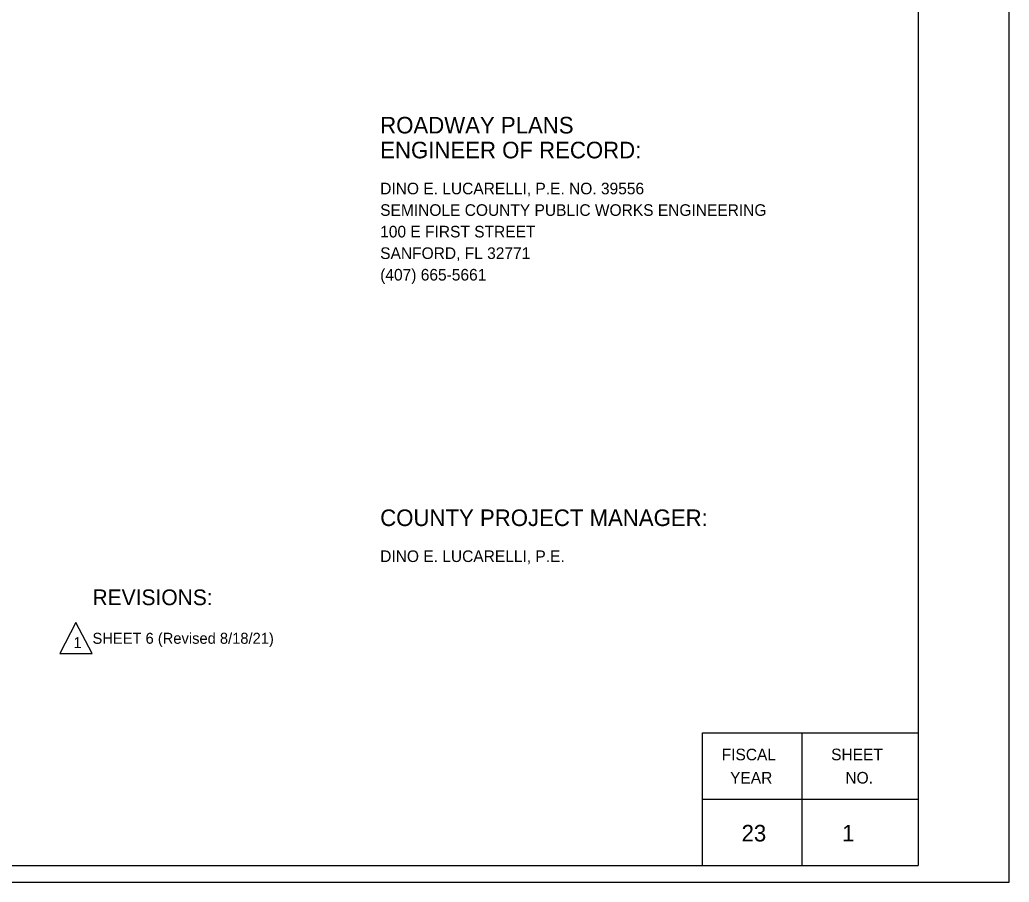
# Model space of a CAD drawing. Extents: x 2157516 to 2331756, y 2153820 to 2265756.
# Drawn here: x 2268726 to 2331756, y 2153820 to 2208739 of the extents above; entities that cross this region are included whole.
import ezdxf

# ---------------------------------------------------------------- set-up
doc = ezdxf.new("R2010")
doc.units = 0
for name, color, linetype in [('NonPlottingEle_dp', 7, 'Continuous'), ('PlotBorder_dp', 7, 'Continuous'), ('SheetBorder_dp', 7, 'Continuous'), ('SheetLines_dp', 7, 'Continuous'), ('TextLabel', 7, 'Continuous'), ('TextNotes', 7, 'Continuous'), ('TextShtNo', 7, 'Continuous')]:
    doc.layers.add(name, color=color, linetype=linetype)

msp = doc.modelspace()

# ---------------------------------------------------------------- linework, layer by layer
at = {"layer": 'NonPlottingEle_dp'}
msp.add_lwpolyline([(2272307, 2170353), (2271280, 2168375), (2273334, 2168375)], close=True, dxfattribs=at)
at = {"layer": 'PlotBorder_dp'}
msp.add_lwpolyline([(2157516, 2153820), (2331756, 2153820), (2331756, 2265756), (2157516, 2265756)], close=True, dxfattribs=at)
at = {"layer": 'SheetBorder_dp'}
for p in [(2325948, 2264700), (2163324, 2154876)]:
    msp.add_line(p, (2325948, 2154876), dxfattribs=at)
at = {"layer": 'SheetLines_dp'}
for p, q in [((2312220, 2163324), (2325948, 2163324)), ((2312220, 2154876), (2312220, 2163324)), ((2318556, 2154876), (2318556, 2163324)), ((2312220, 2159100), (2325948, 2159100))]:
    msp.add_line(p, q, dxfattribs=at)

# ---------------------------------------------------------------- texts
at = {"layer": 'NonPlottingEle_dp'}
for s, height, p in [('REVISIONS:', 1000, (2273359, 2171462)), ('SHEET 6 (Revised 8/18/21)                               ', 700, (2273359, 2169002)), ('1', 700, (2272146, 2168727))]:
    msp.add_text(s, height=height, dxfattribs=at).set_placement(p)
at = {"layer": 'TextLabel'}
for s, p in [('ROADWAY PLANS', (2291686, 2201501)), ('ENGINEER OF RECORD:', (2291686, 2199917)), ('COUNTY PROJECT MANAGER:', (2291686, 2176500))]:
    msp.add_text(s, height=1056, dxfattribs=at).set_placement(p)
at = {"layer": 'TextNotes'}
for s, p in [('DINO E. LUCARELLI, P.E. NO. 39556', (2291686, 2197625)), ('SEMINOLE COUNTY PUBLIC WORKS ENGINEERING', (2291686, 2196253)), ('100 E FIRST STREET', (2291686, 2194880)), ('SANFORD, FL 32771', (2291686, 2193507)), ('(407) 665-5661', (2291686, 2192134)), ('DINO E. LUCARELLI, P.E. ', (2291686, 2174209))]:
    msp.add_text(s, height=739.2, dxfattribs=at).set_placement(p)
for s, p in [('FISCAL', (2313439, 2161586)), ('SHEET', (2320412, 2161586)), ('YEAR', (2313974, 2160106)), ('NO.', (2321317, 2160105))]:
    msp.add_text(s, height=739.2, rotation=359.86066, dxfattribs=at).set_placement(p)
at = {"layer": 'TextShtNo'}
for s, p in [('  23   ', (2313922, 2156414)), ('  1    ', (2320324, 2156414))]:
    msp.add_text(s, height=1056, dxfattribs=at).set_placement(p)

doc.saveas('drawing.dxf')
